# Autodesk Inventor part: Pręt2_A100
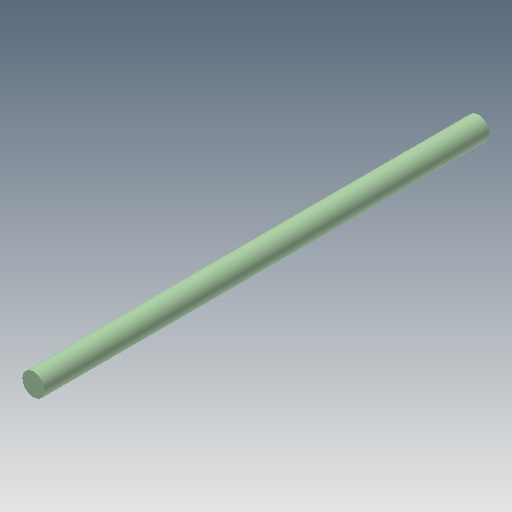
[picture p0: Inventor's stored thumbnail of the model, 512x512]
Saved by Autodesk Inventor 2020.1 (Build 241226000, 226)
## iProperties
Created: 2006-06
Part Number: Pręt2_A100
Document SubType Name: Modeling
Designer: F.Stasiak
Density: 1 g/cm^3
Material: Ogólny
Appearance: Zielony pastelowy
Manager: www.cadconsulting.pl
Company: Fabian Stasiak CAD Consulting
Author: F.Stasiak
Subject: Zbiór ćwiczeń. Autodesk Inventor 2020. Kurs podstawowy
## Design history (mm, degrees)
sketch "Szkic1"
  geometry: C1 r 25 at (0, 0); 1 further point
  constraints: 1 centre point, 1 coincident
  dimensions: "d0" = 50 diameter of C1
extrude "Wyciągnięcie proste1" new body sketch "Szkic1" distance "d1" = 990; taper "d2" = 0 deg
node "Bryła1"
node "Korpusy bryłowe"
node "Korpusy powierzchniowe"
